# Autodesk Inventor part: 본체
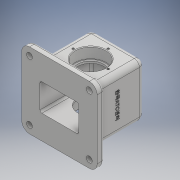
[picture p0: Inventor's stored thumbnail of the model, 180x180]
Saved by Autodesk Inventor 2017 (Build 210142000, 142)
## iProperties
Part Number: 본체
Material: 일반
Document SubType Name: Modeling
Designer: MRC
Density: 1 g/cm^3
Appearance: 기본값
Author: MRC
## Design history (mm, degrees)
sketch "스케치1"
  geometry: L1 (-58, 58)-(58, 58); L2 (58, 58)-(58, -58); L3 (58, -58)-(-58, -58); L4 (-58, -58)-(-58, 58); L5 (-58, 58)-(58, -58); L6 (58, 58)-(-58, -58); 1 further point
  constraints: 12 end point, 2 midpoint, 2 parallel, 2 perpendicular, 1 horizontal
  dimensions: "d0" = 116 distance of L1.end L2.end
extrude "돌출1" new body sketch "스케치1" distance "d1" = 10; taper "d2" = 0 deg
sketch "스케치2" dims "d13" = 12, "d14" = 12, "d15" = 12, "d16" = 12, "d17" = 9
  geometry: L1 (41, -41)-(-41, -41); L2 (-41, -41)-(-41, 41); L3 (-41, 41)-(41, 41); L4 (41, 41)-(41, -41); L5 (41, -41)-(-41, 41); L6 (-41, -41)-(41, 41); 1 further point
  constraints: 12 end point, 2 midpoint, 2 parallel, 2 perpendicular, 1 horizontal
  dimensions: "d3" = 82 distance of L1.end L2.end
extrude "돌출2" join sketch "스케치2" distance "d4" = 80; taper "d5" = 0 deg
sketch "스케치3"
  geometry: L1 (-30, 21)-(30, 21); L2 (30, 21)-(30, -21); L3 (30, -21)-(-30, -21); L4 (-30, -21)-(-30, 21); L5 (-30, 21)-(30, -21); L6 (30, 21)-(-30, -21); 1 further point
  constraints: 12 end point, 2 midpoint, 2 parallel, 1 horizontal, 1 perpendicular
  dimensions: "d6" = 42 distance of L1.end L2.end; "d7" = 60 distance of L2.end L3.end
extrude "돌출3" cut sketch "스케치3" distance "d8" = 80; taper "d9" = 0 deg
sketch "스케치4"
  geometry: C1 r 7.5 at (0, 0); 1 further point
  constraints: 1 centre point, 1 coincident
  dimensions: "d10" = 15 diameter of C1
extrude "돌출4" join sketch "스케치4" distance "d11" = 4; taper "d12" = 0 deg
sketch "스케치5"
  geometry: L1 (58, 58)-(58, -58) reference; L2 (58, -58)-(-58, -58) reference; L3 (-58, -58)-(-58, 58) reference; L4 (-58, 58)-(58, 58) reference; C1 r 4.5 at (46, -46); C2 r 4.5 at (-46, -46); C3 r 4.5 at (-46, 46); C4 r 4.5 at (46, 46); 1 further point
  constraints: 4 centre point, 3 equal radius, 2 horizontal alignment, 2 vertical alignment
  dimensions: "d13" = 12 distance from line of L1 C1.centre; "d14" = 12 distance from line of L2 C1.centre; "d15" = 12 distance from line of L3 C2.centre; "d16" = 12 distance from line of L4 C3.centre; "d17" = 9 diameter of C1
extrude "돌출5" cut sketch "스케치5" distance "d18" = 10; taper "d19" = 0 deg
sketch "스케치6"
  geometry: L1 (99, -10)-(-17, -10) reference; C1 r 23.5 at (41, 38); 2 further points
  constraints: 1 centre point, 1 midpoint, 1 vertical alignment
  dimensions: "d20" = 48 distance from line of L1 C1.centre; "d21" = 47 diameter of C1
extrude "돌출6" cut sketch "스케치6" distance "d22" = 17; taper "d23" = 0 deg
sketch "스케치7"
  geometry: C1 r 20 at (0, 0); C2 r 23.5 at (0, 0) reference; 1 further point
  constraints: 1 centre point, 1 concentric
  dimensions: "d24" = 40 diameter of C1
extrude "돌출7" cut sketch "스케치7" distance "d25" = 3; taper "d26" = 0 deg
sketch "스케치8"
  geometry: C1 r 20 at (41, 38) reference; 5 further points
  constraints: 1 vertical alignment, 5 other
  dimensions: "d27" = 27 distance of C1.centre point (41, 65); "d30" = 360 deg dimension on C1.centre point (41, 65) (derived)
hole "구멍1" sketch "스케치8" at (41, 65), (14, 38), (41, 11), (68, 38) diameter "d32" = 3.242; stored, may be unused: countersink angle "d36" = 90 deg, drill point angle "d38" = 118 deg; dims "d33" = 8, "d34" = 4, "d35" = 2, "d37" = 10
fillet "모깎기1" dims "d39" = 0.6
chamfer "모따기1" distance "d40" = 1; stored, may be unused: second distance "d41" = 2, angle "d42" = 45 deg
hole "구멍2" diameter "d45" = 4.917; stored, may be unused: countersink angle "d49" = 90 deg, drill point angle "d51" = 0 deg; dims "d46" = 17, "d47" = 4, "d48" = 2, "d50" = 17, "d52" = 10, "d53" = 10
chamfer "모따기2" distance "d54" = 1; stored, may be unused: second distance "d55" = 2, angle "d56" = 45 deg
fillet "모깎기2" dims "d57" = 8
fillet "모깎기3" dims "d58" = 8
fillet "모깎기4" dims "d59" = 12
fillet "모깎기5" dims "d60" = 3
sketch "스케치9"
  geometry: L1 (79, -82)-(-13, -82) reference; 3 further points
  constraints: 1 midpoint, 1 vertical alignment, 1 other
  dimensions: "d61" = 48 distance from line of L1 point (33, -34)
extrude "돌출8" join sketch "스케치9" distance "d62" = 0.5; taper "d63" = 0 deg
node "솔리드1"
mirror "미러1"
